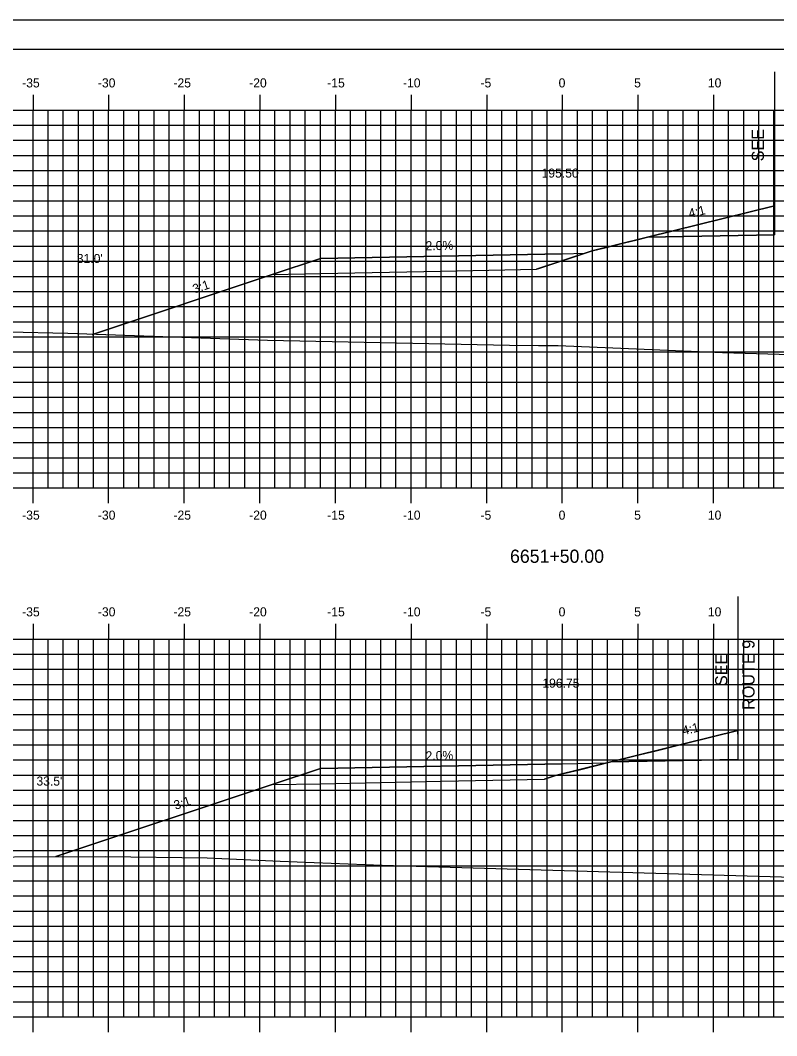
# Model space of a CAD drawing. Extents: x 1723543 to 1723714, y 458501 to 458611.
# Drawn here: x 1723589.9 to 1723640, y 458544 to 458611.2 of the extents above; entities that cross this region are included whole.
import ezdxf

# ---------------------------------------------------------------- set-up
doc = ezdxf.new("R2010")
doc.units = 0
for name, color, linetype in [('ANNOTATION', 7, 'Continuous'), ('BORDER', 7, 'Continuous'), ('D_Roadway_Centerline', 7, 'Continuous'), ('D_Roadway_Centerline_Text', 7, 'Continuous'), ('D_Roadway_Drive_Gravel', 7, 'Continuous'), ('D_Roadway_Edge_Shoulder', 7, 'Continuous'), ('D_Roadway_SlopeLines', 7, 'Continuous'), ('D_Roadway_SubGrade', 7, 'Continuous'), ('D_Text_Standard', 7, 'Continuous'), ('H_V ANNOTATION', 7, 'Continuous'), ('MAJOR', 7, 'Continuous'), ('MINOR', 7, 'Continuous'), ('PLOT BOUNDARY', 7, 'Continuous'), ('S_Roadway_Centerline', 7, 'Continuous')]:
    doc.layers.add(name, color=color, linetype=linetype)

msp = doc.modelspace()

# ---------------------------------------------------------------- linework, layer by layer
for points in [[(1723594.69, 458590.403), (1723594.712, 458590.41), (1723594.722, 458590.413), (1723594.747, 458590.421), (1723594.753, 458590.424), (1723594.784, 458590.434), (1723606.594, 458594.371), (1723609.785, 458595.434), (1723617.785, 458595.594), (1723625.785, 458595.754), (1723627.291, 458595.784)], [(1723592.3, 458555.856), (1723606.594, 458560.621), (1723609.785, 458561.684), (1723617.785, 458561.844), (1723625.785, 458562.004), (1723628.744, 458562.064)]]:
    msp.add_lwpolyline(points)
at = {"layer": 'BORDER'}
msp.add_lwpolyline([(1723550.786, 458504.254), (1723710.786, 458504.254), (1723710.786, 458609.254), (1723550.786, 458609.254)], close=True, dxfattribs=at)
at = {"layer": 'D_Roadway_Centerline'}
for points in [[(1723624.073, 458594.72), (1723624.229, 458594.772), (1723627.764, 458595.941), (1723628.515, 458596.127), (1723629.988, 458596.492), (1723630.657, 458596.658), (1723631.419, 458596.847), (1723632.705, 458597.166), (1723633.196, 458597.287), (1723636.664, 458598.147), (1723639.82, 458598.929)], [(1723624.616, 458560.981), (1723625.343, 458561.221), (1723625.984, 458561.38), (1723626.915, 458561.61), (1723628.125, 458561.91), (1723628.998, 458562.126), (1723630.862, 458562.588), (1723631.989, 458562.867), (1723634.516, 458563.493), (1723637.399, 458564.207)]]:
    msp.add_lwpolyline(points, dxfattribs=at)
at = {"layer": 'D_Roadway_Drive_Gravel'}
for points in [[(1723625.785, 458595.754), (1723617.785, 458595.594), (1723609.785, 458595.434), (1723606.594, 458594.371), (1723609.785, 458594.434), (1723617.785, 458594.594), (1723624.073, 458594.72)], [(1723625.785, 458562.004), (1723617.785, 458561.844), (1723609.785, 458561.684), (1723606.594, 458560.621), (1723609.785, 458560.684), (1723617.785, 458560.844), (1723624.616, 458560.981)]]:
    msp.add_lwpolyline(points, dxfattribs=at)
at = {"layer": 'D_Roadway_Edge_Shoulder'}
for p, q in [((1723639.82, 458598.929), (1723639.82, 458598.679)), ((1723639.82, 458598.929), (1723639.82, 458598.679)), ((1723637.399, 458564.207), (1723637.399, 458563.957)), ((1723637.399, 458564.207), (1723637.399, 458563.957))]:
    msp.add_line(p, q, dxfattribs=at)
at = {"layer": 'D_Roadway_SlopeLines'}
for points in [[(1723639.82, 458598.929), (1723627.764, 458595.941), (1723624.073, 458594.72)], [(1723639.82, 458598.929), (1723627.764, 458595.941), (1723624.073, 458594.72)], [(1723639.82, 458598.929), (1723627.764, 458595.941), (1723624.073, 458594.72)], [(1723639.82, 458598.929), (1723627.764, 458595.941), (1723624.073, 458594.72)], [(1723639.82, 458598.929), (1723627.764, 458595.941), (1723624.073, 458594.72)], [(1723639.82, 458598.929), (1723627.764, 458595.941), (1723624.073, 458594.72)], [(1723639.82, 458598.929), (1723627.764, 458595.941)], [(1723639.82, 458598.929), (1723627.764, 458595.941)], [(1723639.82, 458598.929), (1723631.419, 458596.847)], [(1723625.785, 458595.754), (1723627.291, 458595.784)], [(1723609.785, 458595.434), (1723606.594, 458594.371), (1723594.784, 458590.434)], [(1723637.399, 458564.207), (1723625.343, 458561.221), (1723624.616, 458560.981)], [(1723637.399, 458564.207), (1723625.343, 458561.221), (1723624.616, 458560.981)], [(1723637.399, 458564.207), (1723625.343, 458561.221), (1723624.616, 458560.981)], [(1723637.399, 458564.207), (1723625.343, 458561.221), (1723624.616, 458560.981)], [(1723637.399, 458564.207), (1723625.343, 458561.221), (1723624.616, 458560.981)], [(1723637.399, 458564.207), (1723625.343, 458561.221), (1723624.616, 458560.981)], [(1723637.399, 458564.207), (1723625.343, 458561.221)], [(1723637.399, 458564.207), (1723625.343, 458561.221)], [(1723637.399, 458564.207), (1723628.998, 458562.126)], [(1723625.785, 458562.004), (1723628.744, 458562.064)], [(1723609.785, 458561.684), (1723606.594, 458560.621), (1723592.3, 458555.856)]]:
    msp.add_lwpolyline(points, dxfattribs=at)
at = {"layer": 'D_Roadway_SubGrade'}
for p, q in [((1723639.82, 458607.788), (1723639.82, 458597.006)), ((1723637.399, 458573.066), (1723637.399, 458562.284))]:
    msp.add_line(p, q, dxfattribs=at)
for points in [[(1723639.82, 458597.006), (1723631.419, 458596.847), (1723639.82, 458598.929), (1723639.82, 458598.679)], [(1723639.82, 458598.679), (1723639.82, 458598.929), (1723631.419, 458596.847), (1723639.82, 458597.006)], [(1723639.82, 458597.006), (1723631.419, 458596.847), (1723639.82, 458598.929), (1723639.82, 458598.679)], [(1723639.82, 458597.006), (1723631.419, 458596.847), (1723639.82, 458598.929), (1723639.82, 458598.679)], [(1723637.399, 458562.284), (1723628.998, 458562.126), (1723637.399, 458564.207), (1723637.399, 458563.957)], [(1723637.399, 458563.957), (1723637.399, 458564.207), (1723628.998, 458562.126), (1723637.399, 458562.284)], [(1723637.399, 458562.284), (1723628.998, 458562.126), (1723637.399, 458564.207), (1723637.399, 458563.957)], [(1723637.399, 458562.284), (1723628.998, 458562.126), (1723637.399, 458564.207), (1723637.399, 458563.957)]]:
    msp.add_lwpolyline(points, dxfattribs=at)
at = {"layer": 'MAJOR'}
for p, q in [((1723590.785, 458606.256), (1723590.785, 458605.254)), ((1723595.785, 458606.256), (1723595.785, 458605.254)), ((1723600.785, 458606.256), (1723600.785, 458605.254)), ((1723605.785, 458606.256), (1723605.785, 458605.254)), ((1723610.785, 458606.256), (1723610.785, 458605.254)), ((1723615.785, 458606.256), (1723615.785, 458605.254)), ((1723620.785, 458606.256), (1723620.785, 458605.254)), ((1723625.785, 458606.256), (1723625.785, 458605.254)), ((1723630.785, 458606.256), (1723630.785, 458605.254)), ((1723635.785, 458606.256), (1723635.785, 458605.254)), ((1723555.785, 458605.254), (1723695.785, 458605.254)), ((1723555.785, 458605.254), (1723695.785, 458605.254)), ((1723590.785, 458580.254), (1723590.785, 458605.254)), ((1723595.785, 458580.254), (1723595.785, 458605.254)), ((1723600.785, 458580.254), (1723600.785, 458605.254)), ((1723605.785, 458580.254), (1723605.785, 458605.254)), ((1723610.785, 458580.254), (1723610.785, 458605.254)), ((1723615.785, 458580.254), (1723615.785, 458605.254)), ((1723620.785, 458580.254), (1723620.785, 458605.254)), ((1723625.785, 458580.254), (1723625.785, 458605.254)), ((1723630.785, 458580.254), (1723630.785, 458605.254)), ((1723635.785, 458580.254), (1723635.785, 458605.254)), ((1723555.785, 458600.254), (1723695.785, 458600.254)), ((1723555.785, 458595.254), (1723695.785, 458595.254)), ((1723555.785, 458590.254), (1723695.785, 458590.254)), ((1723555.785, 458585.254), (1723695.785, 458585.254)), ((1723555.785, 458580.254), (1723695.785, 458580.254)), ((1723555.785, 458580.254), (1723695.785, 458580.254)), ((1723590.785, 458579.252), (1723590.785, 458580.254)), ((1723595.785, 458579.252), (1723595.785, 458580.254)), ((1723600.785, 458579.252), (1723600.785, 458580.254)), ((1723605.785, 458579.252), (1723605.785, 458580.254)), ((1723610.785, 458579.252), (1723610.785, 458580.254)), ((1723615.785, 458579.252), (1723615.785, 458580.254)), ((1723620.785, 458579.252), (1723620.785, 458580.254)), ((1723625.785, 458579.252), (1723625.785, 458580.254)), ((1723630.785, 458579.252), (1723630.785, 458580.254)), ((1723635.785, 458579.252), (1723635.785, 458580.254)), ((1723590.785, 458571.256), (1723590.785, 458570.254)), ((1723595.785, 458571.256), (1723595.785, 458570.254)), ((1723600.785, 458571.256), (1723600.785, 458570.254)), ((1723605.785, 458571.256), (1723605.785, 458570.254)), ((1723610.785, 458571.256), (1723610.785, 458570.254)), ((1723615.785, 458571.256), (1723615.785, 458570.254)), ((1723620.785, 458571.256), (1723620.785, 458570.254)), ((1723625.785, 458571.256), (1723625.785, 458570.254)), ((1723630.785, 458571.256), (1723630.785, 458570.254)), ((1723635.785, 458571.256), (1723635.785, 458570.254)), ((1723555.785, 458570.254), (1723695.785, 458570.254)), ((1723555.785, 458570.254), (1723695.785, 458570.254)), ((1723590.785, 458545.254), (1723590.785, 458570.254)), ((1723595.785, 458545.254), (1723595.785, 458570.254)), ((1723600.785, 458545.254), (1723600.785, 458570.254)), ((1723605.785, 458545.254), (1723605.785, 458570.254)), ((1723610.785, 458545.254), (1723610.785, 458570.254)), ((1723615.785, 458545.254), (1723615.785, 458570.254)), ((1723620.785, 458545.254), (1723620.785, 458570.254)), ((1723625.785, 458545.254), (1723625.785, 458570.254)), ((1723630.785, 458545.254), (1723630.785, 458570.254)), ((1723635.785, 458545.254), (1723635.785, 458570.254)), ((1723555.785, 458565.254), (1723695.785, 458565.254)), ((1723555.785, 458560.254), (1723695.785, 458560.254)), ((1723555.785, 458555.254), (1723695.785, 458555.254)), ((1723555.785, 458550.254), (1723695.785, 458550.254)), ((1723555.785, 458545.254), (1723695.785, 458545.254)), ((1723555.785, 458545.254), (1723695.785, 458545.254)), ((1723590.785, 458544.252), (1723590.785, 458545.254)), ((1723595.785, 458544.252), (1723595.785, 458545.254)), ((1723600.785, 458544.252), (1723600.785, 458545.254)), ((1723605.785, 458544.252), (1723605.785, 458545.254)), ((1723610.785, 458544.252), (1723610.785, 458545.254)), ((1723615.785, 458544.252), (1723615.785, 458545.254)), ((1723620.785, 458544.252), (1723620.785, 458545.254)), ((1723625.785, 458544.252), (1723625.785, 458545.254)), ((1723630.785, 458544.252), (1723630.785, 458545.254)), ((1723635.785, 458544.252), (1723635.785, 458545.254))]:
    msp.add_line(p, q, dxfattribs=at)
at = {"layer": 'MINOR'}
for p, q in [((1723591.785, 458580.254), (1723591.785, 458605.254)), ((1723592.785, 458580.254), (1723592.785, 458605.254)), ((1723593.785, 458580.254), (1723593.785, 458605.254)), ((1723594.785, 458580.254), (1723594.785, 458605.254)), ((1723596.785, 458580.254), (1723596.785, 458605.254)), ((1723597.785, 458580.254), (1723597.785, 458605.254)), ((1723598.785, 458580.254), (1723598.785, 458605.254)), ((1723599.785, 458580.254), (1723599.785, 458605.254)), ((1723601.785, 458580.254), (1723601.785, 458605.254)), ((1723602.785, 458580.254), (1723602.785, 458605.254)), ((1723603.785, 458580.254), (1723603.785, 458605.254)), ((1723604.785, 458580.254), (1723604.785, 458605.254)), ((1723606.785, 458580.254), (1723606.785, 458605.254)), ((1723607.785, 458580.254), (1723607.785, 458605.254)), ((1723608.785, 458580.254), (1723608.785, 458605.254)), ((1723609.785, 458580.254), (1723609.785, 458605.254)), ((1723611.785, 458580.254), (1723611.785, 458605.254)), ((1723612.785, 458580.254), (1723612.785, 458605.254)), ((1723613.785, 458580.254), (1723613.785, 458605.254)), ((1723614.785, 458580.254), (1723614.785, 458605.254)), ((1723616.785, 458580.254), (1723616.785, 458605.254)), ((1723617.785, 458580.254), (1723617.785, 458605.254)), ((1723618.785, 458580.254), (1723618.785, 458605.254)), ((1723619.785, 458580.254), (1723619.785, 458605.254)), ((1723621.785, 458580.254), (1723621.785, 458605.254)), ((1723622.785, 458580.254), (1723622.785, 458605.254)), ((1723623.785, 458580.254), (1723623.785, 458605.254)), ((1723624.785, 458580.254), (1723624.785, 458605.254)), ((1723626.785, 458580.254), (1723626.785, 458605.254)), ((1723627.785, 458580.254), (1723627.785, 458605.254)), ((1723628.785, 458580.254), (1723628.785, 458605.254)), ((1723629.785, 458580.254), (1723629.785, 458605.254)), ((1723631.785, 458580.254), (1723631.785, 458605.254)), ((1723632.785, 458580.254), (1723632.785, 458605.254)), ((1723633.785, 458580.254), (1723633.785, 458605.254)), ((1723634.785, 458580.254), (1723634.785, 458605.254)), ((1723636.785, 458580.254), (1723636.785, 458605.254)), ((1723637.785, 458580.254), (1723637.785, 458605.254)), ((1723638.785, 458580.254), (1723638.785, 458605.254)), ((1723639.785, 458580.254), (1723639.785, 458605.254)), ((1723555.785, 458604.254), (1723695.785, 458604.254)), ((1723555.785, 458603.254), (1723695.785, 458603.254)), ((1723555.785, 458602.254), (1723695.785, 458602.254)), ((1723555.785, 458601.254), (1723695.785, 458601.254)), ((1723555.785, 458599.254), (1723695.785, 458599.254)), ((1723555.785, 458598.254), (1723695.785, 458598.254)), ((1723555.785, 458597.254), (1723695.785, 458597.254)), ((1723555.785, 458596.254), (1723695.785, 458596.254)), ((1723555.785, 458594.254), (1723695.785, 458594.254)), ((1723555.785, 458593.254), (1723695.785, 458593.254)), ((1723555.785, 458592.254), (1723695.785, 458592.254)), ((1723555.785, 458591.254), (1723695.785, 458591.254)), ((1723555.785, 458589.254), (1723695.785, 458589.254)), ((1723555.785, 458588.254), (1723695.785, 458588.254)), ((1723555.785, 458587.254), (1723695.785, 458587.254)), ((1723555.785, 458586.254), (1723695.785, 458586.254)), ((1723555.785, 458584.254), (1723695.785, 458584.254)), ((1723555.785, 458583.254), (1723695.785, 458583.254)), ((1723555.785, 458582.254), (1723695.785, 458582.254)), ((1723555.785, 458581.254), (1723695.785, 458581.254)), ((1723591.785, 458545.254), (1723591.785, 458570.254)), ((1723592.785, 458545.254), (1723592.785, 458570.254)), ((1723593.785, 458545.254), (1723593.785, 458570.254)), ((1723594.785, 458545.254), (1723594.785, 458570.254)), ((1723596.785, 458545.254), (1723596.785, 458570.254)), ((1723597.785, 458545.254), (1723597.785, 458570.254)), ((1723598.785, 458545.254), (1723598.785, 458570.254)), ((1723599.785, 458545.254), (1723599.785, 458570.254)), ((1723601.785, 458545.254), (1723601.785, 458570.254)), ((1723602.785, 458545.254), (1723602.785, 458570.254)), ((1723603.785, 458545.254), (1723603.785, 458570.254)), ((1723604.785, 458545.254), (1723604.785, 458570.254)), ((1723606.785, 458545.254), (1723606.785, 458570.254)), ((1723607.785, 458545.254), (1723607.785, 458570.254)), ((1723608.785, 458545.254), (1723608.785, 458570.254)), ((1723609.785, 458545.254), (1723609.785, 458570.254)), ((1723611.785, 458545.254), (1723611.785, 458570.254)), ((1723612.785, 458545.254), (1723612.785, 458570.254)), ((1723613.785, 458545.254), (1723613.785, 458570.254)), ((1723614.785, 458545.254), (1723614.785, 458570.254)), ((1723616.785, 458545.254), (1723616.785, 458570.254)), ((1723617.785, 458545.254), (1723617.785, 458570.254)), ((1723618.785, 458545.254), (1723618.785, 458570.254)), ((1723619.785, 458545.254), (1723619.785, 458570.254)), ((1723621.785, 458545.254), (1723621.785, 458570.254)), ((1723622.785, 458545.254), (1723622.785, 458570.254)), ((1723623.785, 458545.254), (1723623.785, 458570.254)), ((1723624.785, 458545.254), (1723624.785, 458570.254)), ((1723626.785, 458545.254), (1723626.785, 458570.254)), ((1723627.785, 458545.254), (1723627.785, 458570.254)), ((1723628.785, 458545.254), (1723628.785, 458570.254)), ((1723629.785, 458545.254), (1723629.785, 458570.254)), ((1723631.785, 458545.254), (1723631.785, 458570.254)), ((1723632.785, 458545.254), (1723632.785, 458570.254)), ((1723633.785, 458545.254), (1723633.785, 458570.254)), ((1723634.785, 458545.254), (1723634.785, 458570.254)), ((1723636.785, 458545.254), (1723636.785, 458570.254)), ((1723637.785, 458545.254), (1723637.785, 458570.254)), ((1723638.785, 458545.254), (1723638.785, 458570.254)), ((1723639.785, 458545.254), (1723639.785, 458570.254)), ((1723555.785, 458569.254), (1723695.785, 458569.254)), ((1723555.785, 458568.254), (1723695.785, 458568.254)), ((1723555.785, 458567.254), (1723695.785, 458567.254)), ((1723555.785, 458566.254), (1723695.785, 458566.254)), ((1723555.785, 458564.254), (1723695.785, 458564.254)), ((1723555.785, 458563.254), (1723695.785, 458563.254)), ((1723555.785, 458562.254), (1723695.785, 458562.254)), ((1723555.785, 458561.254), (1723695.785, 458561.254)), ((1723555.785, 458559.254), (1723695.785, 458559.254)), ((1723555.785, 458558.254), (1723695.785, 458558.254)), ((1723555.785, 458557.254), (1723695.785, 458557.254)), ((1723555.785, 458556.254), (1723695.785, 458556.254)), ((1723555.785, 458554.254), (1723695.785, 458554.254)), ((1723555.785, 458553.254), (1723695.785, 458553.254)), ((1723555.785, 458552.254), (1723695.785, 458552.254)), ((1723555.785, 458551.254), (1723695.785, 458551.254)), ((1723555.785, 458549.254), (1723695.785, 458549.254)), ((1723555.785, 458548.254), (1723695.785, 458548.254)), ((1723555.785, 458547.254), (1723695.785, 458547.254)), ((1723555.785, 458546.254), (1723695.785, 458546.254))]:
    msp.add_line(p, q, dxfattribs=at)
at = {"layer": 'PLOT BOUNDARY'}
msp.add_lwpolyline([(1723542.692, 458501.195), (1723712.692, 458501.195), (1723712.692, 458611.195), (1723542.692, 458611.195)], close=True, dxfattribs=at)
at = {"layer": 'S_Roadway_Centerline'}
for points in [[(1723555.785, 458591.47), (1723562.634, 458591.225), (1723564.833, 458591.119), (1723566.056, 458591.128), (1723573.85, 458590.931), (1723586.854, 458590.649), (1723589.146, 458590.577), (1723593.094, 458590.494), (1723606.299, 458590.024), (1723622.288, 458589.703), (1723624.211, 458589.684), (1723625.504, 458589.67), (1723636.39, 458589.225), (1723646.889, 458588.895), (1723648.382, 458588.881), (1723666.137, 458588.667), (1723680.866, 458588.185), (1723683.212, 458588.086), (1723684.599, 458588.051), (1723694.44, 458587.568), (1723695.785, 458587.47)], [(1723555.785, 458556.489), (1723564.545, 458556.413), (1723571.514, 458556.395), (1723582.117, 458555.861), (1723583.488, 458555.828), (1723595.581, 458555.866), (1723602.294, 458555.786), (1723607.123, 458555.553), (1723613.878, 458555.293), (1723623.634, 458555.001), (1723642.551, 458554.449), (1723642.611, 458554.446), (1723642.654, 458554.445), (1723642.863, 458554.44), (1723662.248, 458553.975), (1723671.582, 458553.786), (1723678.391, 458553.664), (1723682.357, 458553.433), (1723689.959, 458553.132), (1723695.785, 458552.954)]]:
    msp.add_lwpolyline(points, dxfattribs=at)

# ---------------------------------------------------------------- texts
at = {"layer": 'ANNOTATION'}
for s, height, rotation, p in [('SEE', 0.8, 90, (1723639.118, 458601.862)), ('4:1', 0.6, 13.61624, (1723634.212, 458598.111)), ('2.0%', 0.6, 1.14576, (1723616.749, 458595.974)), ('3:1', 0.6, 18.43495, (1723601.454, 458593.111)), ('ROUTE 9', 0.8, 90, (1723638.497, 458565.566)), ('SEE', 0.8, 90, (1723636.697, 458567.141)), ('4:1', 0.6, 13.61624, (1723633.797, 458563.887)), ('2.0%', 0.6, 1.14576, (1723616.749, 458562.224)), ('3:1', 0.6, 18.43495, (1723600.212, 458558.947))]:
    msp.add_text(s, height=height, rotation=rotation, dxfattribs=at).set_placement(p)
at = {"layer": 'D_Roadway_Centerline_Text'}
for s, p in [('195.50', (1723624.415, 458600.786)), ('196.75', (1723624.466, 458567.036))]:
    msp.add_text(s, height=0.6, dxfattribs=at).set_placement(p)
at = {"layer": 'D_Text_Standard'}
for s, p in [("31.0'", (1723593.679, 458595.134)), ("33.5'", (1723591.008, 458560.556))]:
    msp.add_text(s, height=0.6, dxfattribs=at).set_placement(p)
at = {"layer": 'H_V ANNOTATION'}
for s, height, p in [('-35', 0.6, (1723590.066, 458606.754)), ('-30', 0.6, (1723595.074, 458606.754)), ('-25', 0.6, (1723600.071, 458606.754)), ('-20', 0.6, (1723605.079, 458606.754)), ('-15', 0.6, (1723610.242, 458606.754)), ('-10', 0.6, (1723615.25, 458606.754)), ('-5', 0.6, (1723620.376, 458606.754)), ('0', 0.6, (1723625.544, 458606.754)), ('5', 0.6, (1723630.536, 458606.754)), ('10', 0.6, (1723635.411, 458606.754)), ('-35', 0.6, (1723590.066, 458578.154)), ('-30', 0.6, (1723595.074, 458578.154)), ('-25', 0.6, (1723600.071, 458578.154)), ('-20', 0.6, (1723605.079, 458578.154)), ('-15', 0.6, (1723610.242, 458578.154)), ('-10', 0.6, (1723615.25, 458578.154)), ('-5', 0.6, (1723620.376, 458578.154)), ('0', 0.6, (1723625.544, 458578.154)), ('5', 0.6, (1723630.536, 458578.154)), ('10', 0.6, (1723635.411, 458578.154)), ('6651+50.00', 0.875, (1723622.329, 458575.297)), ('-35', 0.6, (1723590.066, 458571.754)), ('-30', 0.6, (1723595.074, 458571.754)), ('-25', 0.6, (1723600.071, 458571.754)), ('-20', 0.6, (1723605.079, 458571.754)), ('-15', 0.6, (1723610.242, 458571.754)), ('-10', 0.6, (1723615.25, 458571.754)), ('-5', 0.6, (1723620.376, 458571.754)), ('0', 0.6, (1723625.544, 458571.754)), ('5', 0.6, (1723630.536, 458571.754)), ('10', 0.6, (1723635.411, 458571.754))]:
    msp.add_text(s, height=height, dxfattribs=at).set_placement(p)

doc.saveas('drawing.dxf')
